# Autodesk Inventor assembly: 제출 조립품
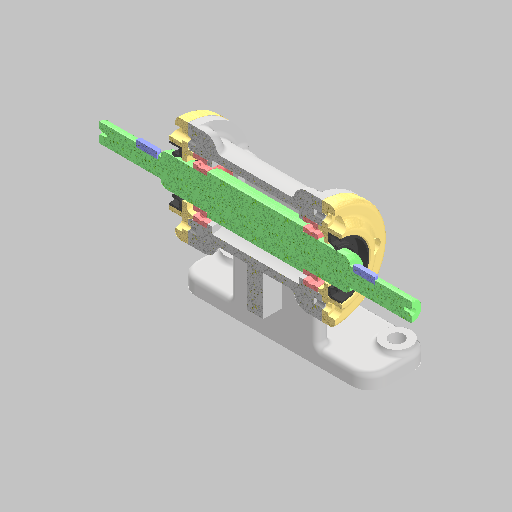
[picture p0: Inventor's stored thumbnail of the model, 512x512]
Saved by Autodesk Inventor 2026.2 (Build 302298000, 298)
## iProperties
Created: 2026-06
Part Number: 제출 조립품
Document SubType Name: Assembly
Designer: sec7
Author: sec7
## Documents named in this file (7)
- C:\Users\sec7\Desktop\최진선\제출 조립품.iam
- C:\Users\sec7\Desktop\최진선\본체.ipt
- C:\Users\sec7\Desktop\최진선\축.ipt
- C:\Users\sec7\Desktop\최진선\평행 키 4x4x14.ipt
- C:\Users\sec7\Desktop\최진선\커버.ipt
- C:\Users\sec7\Desktop\최진선\오일 실 20 35 8.ipt
- C:\Users\sec7\Desktop\최진선\깊은 홈 볼 베어링 6904.ipt
